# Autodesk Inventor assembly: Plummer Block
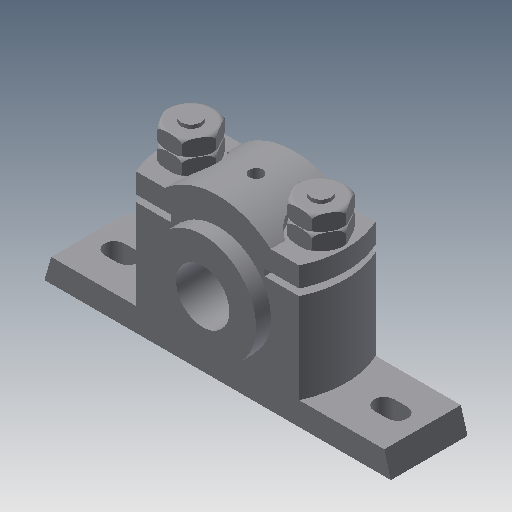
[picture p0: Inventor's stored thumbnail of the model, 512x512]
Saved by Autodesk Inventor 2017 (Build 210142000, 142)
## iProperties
Created: 2011-07
Part Number: Plummer Block
Document SubType Name: Assembly
Designer: CadCim
Author: CadCim
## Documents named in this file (7)
- D:\KAVITA\Autodesk Inventor_ 2016 Project_Kavita\Inventor_Part Files\Inventor_2016_Part\c11_Inv_2016\c11_inv_2016_prt\fig 11-40 through 11-45\Plummer Block.iam
- D:\KAVITA\Autodesk Inventor_ 2016 Project_Kavita\Inventor_Part Files\Inventor_2016_Part\c11_Inv_2016\c11_inv_2016_prt\fig 11-40 through 11-45\Casting.ipt
- D:\KAVITA\Autodesk Inventor_ 2016 Project_Kavita\Inventor_Part Files\Inventor_2016_Part\c11_Inv_2016\c11_inv_2016_prt\fig 11-40 through 11-45\Brasses.ipt
- D:\KAVITA\Autodesk Inventor_ 2016 Project_Kavita\Inventor_Part Files\Inventor_2016_Part\c11_Inv_2016\c11_inv_2016_prt\fig 11-40 through 11-45\Cap.ipt
- D:\KAVITA\Autodesk Inventor_ 2016 Project_Kavita\Inventor_Part Files\Inventor_2016_Part\c11_Inv_2016\c11_inv_2016_prt\fig 11-40 through 11-45\Bolt.ipt
- D:\KAVITA\Autodesk Inventor_ 2016 Project_Kavita\Inventor_Part Files\Inventor_2016_Part\c11_Inv_2016\c11_inv_2016_prt\fig 11-40 through 11-45\Nut.ipt
- D:\KAVITA\Autodesk Inventor_ 2016 Project_Kavita\Inventor_Part Files\Inventor_2016_Part\c11_Inv_2016\c11_inv_2016_prt\fig 11-40 through 11-45\Lock Nut.ipt
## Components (9 placed, 6 different names)
1. Casting:1 — Mate:1, Mate:2, Insert:1, Insert:2, Angle:1, Angle:2
2. Brasses:1 — Mate:1, Mate:2, Mate:3, Mate:4
3. Cap:1 — Mate:3, Mate:4, Insert:3, Insert:4
4. Bolt:1 — Insert:1, Angle:1
5. Bolt:2 — Insert:2, Angle:2
6. Nut:1 — Insert:3, Insert:6
7. Nut:2 — Insert:4, Insert:5
8. Lock Nut:1 — Insert:6
9. Lock Nut:2 — Insert:5
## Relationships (12: Insert 6, Mate 4, Angle 2)
- Mate:1: Casting:1 ↔ Brasses:1
- Mate:2: Casting:1 ↔ Brasses:1
- Mate:3: Brasses:1 ↔ Cap:1
- Mate:4: Brasses:1 ↔ Cap:1
- Insert:1: Casting:1 ↔ Bolt:1
- Insert:2: Casting:1 ↔ Bolt:2
- Angle:1: Casting:1 ↔ Bolt:1
- Angle:2: Casting:1 ↔ Bolt:2
- Insert:3: Cap:1 ↔ Nut:1
- Insert:4: Cap:1 ↔ Nut:2
- Insert:5: Nut:2 ↔ Lock Nut:2
- Insert:6: Nut:1 ↔ Lock Nut:1
